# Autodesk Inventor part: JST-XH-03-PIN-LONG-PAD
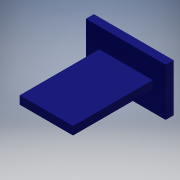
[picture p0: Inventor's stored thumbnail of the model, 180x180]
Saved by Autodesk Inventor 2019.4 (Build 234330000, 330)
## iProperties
Created: 2019-11
Part Number: JST-XH-03-PIN-LONG-PAD
Material: Generic
Document SubType Name: Modeling
Designer: Willist
Density: 1 g/cm^3
Appearance: JST-XH-03-PACKAGE-LONG-PAD, JST-XH-03-PIN-LONG-PAD
Author: Willist
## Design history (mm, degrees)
sketch "JST-XH-03-PACKAGE-LONG-PAD, JST-XH-03-PIN-LONG-PAD_147"
  geometry: L1 (-4.95, 3.519)-(5.077, 3.519); L2 (5.077, 3.519)-(5.077, -2.485); L3 (5.077, -2.485)-(-4.95, -2.485); L4 (-4.95, -2.485)-(-4.95, 3.519)
  constraints: 8 end point
extrude "Extrusion1" join sketch "JST-XH-03-PACKAGE-LONG-PAD, JST-XH-03-PIN-LONG-PAD_147" distance "d0" = 1; taper "d1" = 0 deg
sketch "Sketch2"
  geometry: L1 (3.435, 1.035)-(-3.265, 1.035); L2 (-3.265, 1.035)-(-3.265, 0); L3 (-3.265, 0)-(3.435, 0); L4 (3.435, 0)-(3.435, 1.035); L5 (3.435, 1.035)-(-3.265, 0); L6 (-3.265, 1.035)-(3.435, 0); 2 further points
  constraints: 12 end point, 2 midpoint, 2 parallel, 1 horizontal, 1 perpendicular
extrude "Extrusion2" join sketch "Sketch2" distance "d2" = 10; taper "d3" = 0 deg
body "Solid1"
